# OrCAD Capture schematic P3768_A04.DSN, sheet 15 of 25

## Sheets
15 0010_PRE-REG 3V3: size Custom
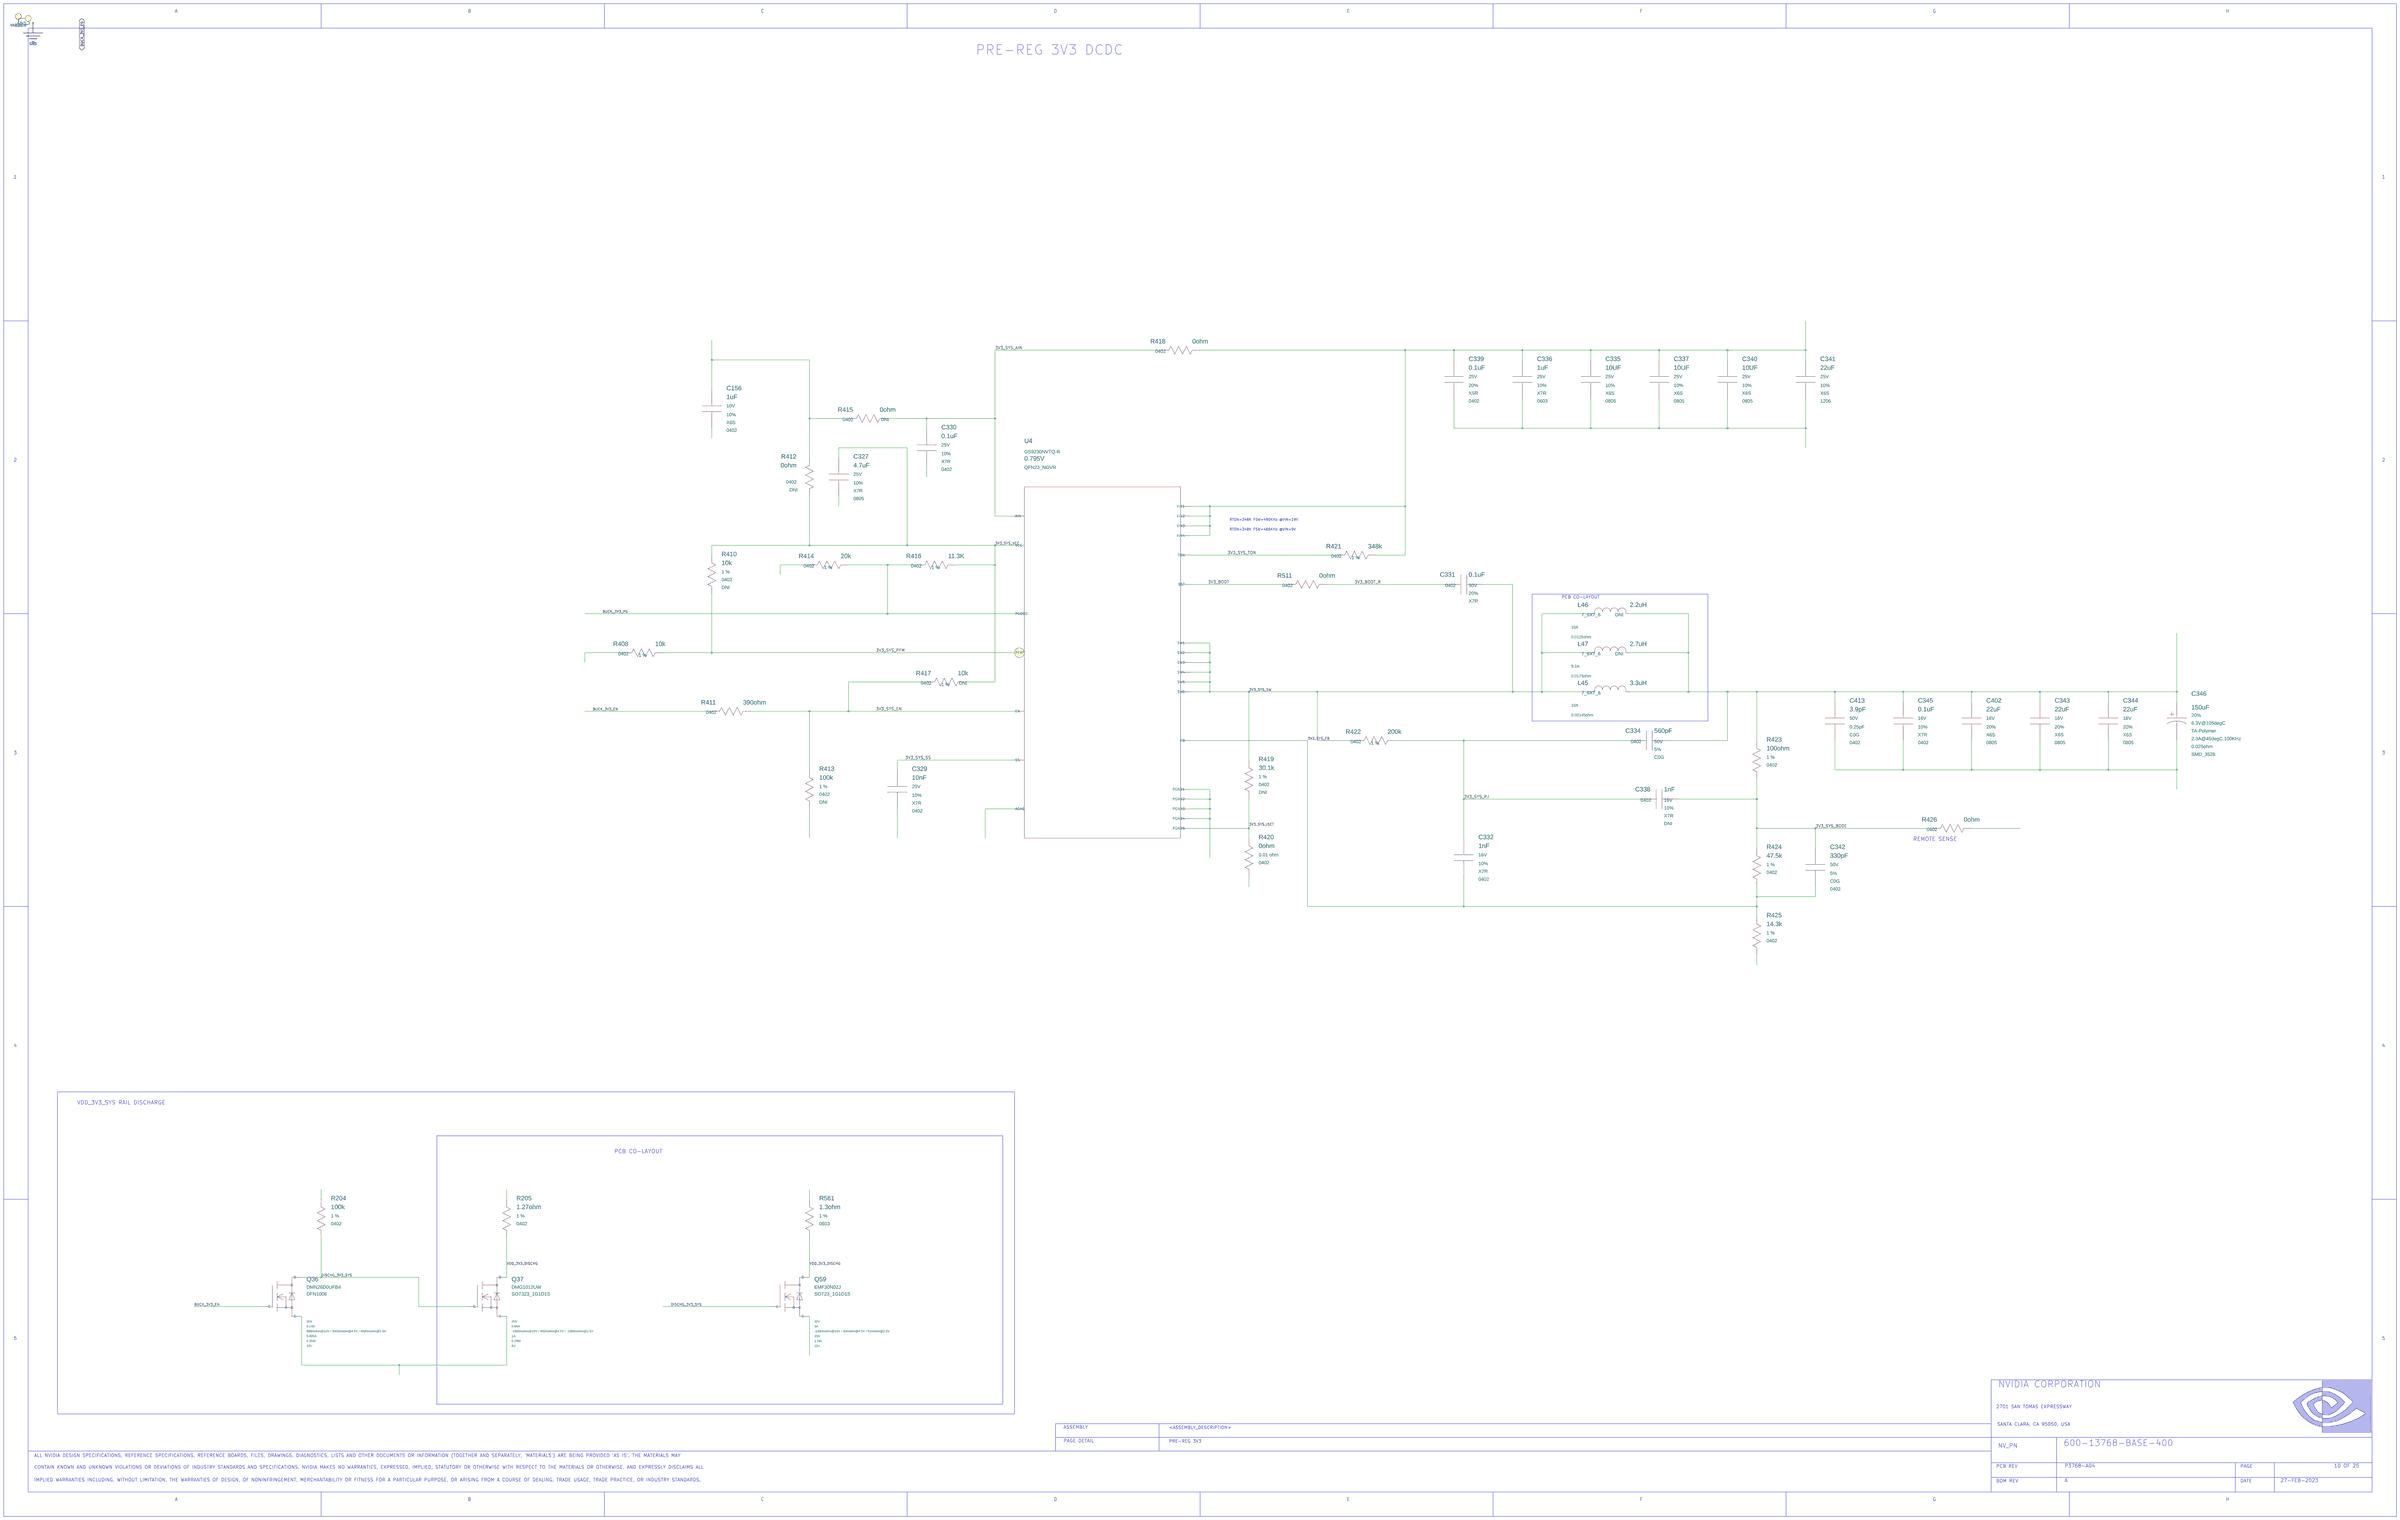
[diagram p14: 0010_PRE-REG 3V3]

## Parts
C156  1uF  [0402]
C327  4.7uF  [0805U]
C329  10nF  [0402]
C330  0.1uF  [0402]
C331  0.1uF  [0402]
C332  1nF  [0402]
C334  560pF  [0402]
C335  10UF  [0805U]
C336  1uF  [0603]
C337  10UF  [0805U]
C338  1nF  [0402]
C339  0.1uF  [0402]
C340  10UF  [0805U]
C341  22uF  [1206U]
C342  330pF  [0402]
C343  22uF  [0805U]
C344  22uF  [0805U]
C345  0.1uF  [0402]
C346  150uF  [CAP_SMD_3528]
C402  22uF  [0805U]
C413  3.9pF  [0402]
L45  3.3uH  [IND_NONRKO_SMD_075X075_B]
L46  2.2uH  [IND_NONRKO_SMD_069X069]
L47  2.7uH  [IND_NONRKO_SMD_075X075_B]
Q36  Q_FET_N_ENH  [DFET_003_SMD_010X006_B]
Q37  Q_FET_N_ENH  [SOT323]
Q59  Q_FET_N_ENH  [SOT23]
R204  100k  [0402]
R205  1.27ohm  [0402]
R408  10k  [0402]
R410  10k  [0402]
R411  390ohm  [0402]
R412  0ohm  [0402]
R413  100k  [0402]
R414  20k  [0402]
R415  0ohm  [0402]
R416  11.3K  [0402]
R417  10k  [0402]
R418  0ohm  [0402]
R419  30.1k  [0402]
R420  0ohm  [0402]
R421  348k  [0402]
R422  200k  [0402]
R423  100ohm  [0402]
R424  47.5k  [0402]
R425  14.3k  [0402]
R426  0ohm  [0402]
R511  0ohm  [0402]
R561  1.3ohm  [0603]
U4  0.795V  [QFN023Q_P050_0040_T028X011_T028X014]

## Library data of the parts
C156 = C#1: ASSEMBLY: PS_3V3; CDS_LIB: discrete; CDS_PART_NAME: C_0402-1UF,X6S,10%,10V,032-0776-000; CDS_PHYS_PART_NAME: C_0402-1UF,X6S,10%,10V,032-0776-000-032-0776-000,1UF; CDS_SEC: 1; CHIPS_PART_NAME: C; DEVICE_TYPENAME: C_0402-1UFX6S1010V032-0776-000-032-0776-0001UF; DRAWING: @P3768_A04_LIB.P3768_A04(SCH_1):PAGE10; MAT: X6S; MAX_VOLTAGE: 10V; NV_PN: 032-0776-000; PATH: I129; PHYS_PAGE: 10; PSPICETEMPLATE: X^@REFDES  %1    %2   @NV_PN; ROT: 0; SEC: 1; SIGNAL_MODEL: nv_cap; TOL: 10%; VER: 1; XY: (-8500,5550)
C327 = C#1: ASSEMBLY: PS_3V3; CDS_LIB: discrete; CDS_PART_NAME: C_0805-4.7UF,X7R,10%,25V,032-0207-000; CDS_PHYS_PART_NAME: C_0805-4.7UF,X7R,10%,25V,032-0207-000-032-0207-000,4.7UF; CDS_SEC: 1; CHIPS_PART_NAME: C; DEVICE_TYPENAME: C_0805-47UFX7R1025V032-0207-000-032-0207-00047UF; DRAWING: @P3768_A04_LIB.P3768_A04(SCH_1):PAGE10; MAT: X7R; MAX_VOLTAGE: 25V; NV_PN: 032-0207-000; PACK_TYPE: 0805; PATH: I80; PHYS_PAGE: 10; PSPICETEMPLATE: X^@REFDES  %1    %2   @NV_PN; ROT: 0; SEC: 1; SIGNAL_MODEL: nv_cap; TOL: 10%; VER: 1; XY: (-7850,5200)
C329 = C#1: ASSEMBLY: PS_3V3; CDS_LIB: discrete; CDS_PART_NAME: C_0402-10NF,X7R,10%,25V,036-0019-000; CDS_PHYS_PART_NAME: C_0402-10NF,X7R,10%,25V,036-0019-000-036-0019-000,10NF; CDS_SEC: 1; CHIPS_PART_NAME: C; DEVICE_TYPENAME: C_0402-10NFX7R1025V036-0019-000-036-0019-00010NF; DRAWING: @P3768_A04_LIB.P3768_A04(SCH_1):PAGE10; MAT: X7R; MAX_VOLTAGE: 25V; NV_PN: 036-0019-000; PATH: I117; PHYS_PAGE: 10; PSPICETEMPLATE: X^@REFDES  %1    %2   @NV_PN; ROT: 0; SEC: 1; SIGNAL_MODEL: nv_cap; TOL: 10%; VER: 1; XY: (-7550,3600)
C330 = C#1: ASSEMBLY: PS_3V3; CDS_LIB: discrete; CDS_PART_NAME: C_0402-0.1UF,X7R,10%,25V,032-1700-000; CDS_PHYS_PART_NAME: C_0402-0.1UF,X7R,10%,25V,032-1700-000-0.1UF,032-1700-000; CDS_SEC: 1; CHIPS_PART_NAME: C; DEVICE_TYPENAME: C_0402-01UFX7R1025V032-1700-000-01UF032-1700-000; DRAWING: @P3768_A04_LIB.P3768_A04(SCH_1):PAGE10; MAT: X7R; MAX_VOLTAGE: 25V; NV_PN: 032-1700-000; PATH: I83; PHYS_PAGE: 10; PSPICETEMPLATE: X^@REFDES  %1    %2   @NV_PN; ROT: 0; SEC: 1; SIGNAL_MODEL: nv_cap; TOL: 10%; VER: 1; XY: (-7400,5350)
C331 = C: ASSEMBLY: PS_5V; CDS_LIB: discrete; CDS_PART_NAME: C_0402-0.1UF,X7R,20%,50V,032-0892-000; CDS_PHYS_PART_NAME: C_0402-0.1UF,X7R,20%,50V,032-0892-000-0.1UF,032-0892-000; CDS_SEC: 1; DEVICE_TYPENAME: C_0402-01UFX7R2050V032-0892-000-01UF032-0892-000; DRAWING: @P3768_A04_LIB.P3768_A04(SCH_1):PAGE10; MAT: X7R; MAX_VOLTAGE: 50V; NV_PN: 032-0892-000; PATH: I87; PHYS_PAGE: 10; PSPICETEMPLATE: X^@REFDES  %1    %2   @NV_PN; ROT: 0; SEC: 1; SIGNAL_MODEL: nv_cap; TOL: 20%; VER: 2; XY: (-4650,4650)
C332 = C#1: ASSEMBLY: PS_3V3; CDS_LIB: discrete; CDS_PART_NAME: C_0402-1NF,X7R,10%,16V,036-0012-000; CDS_PHYS_PART_NAME: C_0402-1NF,X7R,10%,16V,036-0012-000-036-0012-000,1NF; CDS_SEC: 1; CHIPS_PART_NAME: C; DEVICE_TYPENAME: C_0402-1NFX7R1016V036-0012-000-036-0012-0001NF; DRAWING: @P3768_A04_LIB.P3768_A04(SCH_1):PAGE10; MAT: X7R; MAX_VOLTAGE: 16V; NV_PN: 036-0012-000; PATH: I124; PHYS_PAGE: 10; PSPICETEMPLATE: X^@REFDES  %1    %2   @NV_PN; ROT: 0; SEC: 1; SIGNAL_MODEL: nv_cap; TOL: 10%; VER: 1; XY: (-4650,3250)
C334 = C: ASSEMBLY: PS_3V3; CDS_LIB: discrete; CDS_PART_NAME: C_0402-560PF,C0G,5%,50V,035-0295-000; CDS_PHYS_PART_NAME: C_0402-560PF,C0G,5%,50V,035-0295-000-035-0295-000,560PF; CDS_SEC: 1; DEVICE_TYPENAME: C_0402-560PFC0G550V035-0295-000-035-0295-000560PF; DRAWING: @P3768_A04_LIB.P3768_A04(SCH_1):PAGE10; MAT: C0G; MAX_VOLTAGE: 50V; NV_PN: 035-0295-000; PATH: I183; PHYS_PAGE: 10; ROT: 0; SEC: 1; SIGNAL_MODEL: nv_cap; TOL: 5%; VER: 2; XY: (-3700,3850)
C335 = C#1: ASSEMBLY: PS_3V3; CDS_LIB: discrete; CDS_PART_NAME: C_0805-10UF,X6S,10%,25V,032-0728-000; CDS_PHYS_PART_NAME: C_0805-10UF,X6S,10%,25V,032-0728-000-032-0728-000,10UF; CDS_SEC: 1; CHIPS_PART_NAME: C; DEVICE_TYPENAME: C_0805-10UFX6S1025V032-0728-000-032-0728-00010UF; DRAWING: @P3768_A04_LIB.P3768_A04(SCH_1):PAGE10; MAT: X6S; MAX_VOLTAGE: 25V; NV_PN: 032-0728-000; PACK_TYPE: 0805; PATH: I151; PHYS_PAGE: 10; PSPICETEMPLATE: X^@REFDES  %1    %2   @NV_PN; ROT: 0; SEC: 1; SIGNAL_MODEL: nv_cap; TOL: 10%; VER: 1; XY: (-4000,5700)
C336 = C#1: ASSEMBLY: PS_3V3; CDS_LIB: discrete; CDS_PART_NAME: C_0603-1UF,X7R,10%,25V,032-0253-000; CDS_PHYS_PART_NAME: C_0603-1UF,X7R,10%,25V,032-0253-000-032-0253-000,1UF; CDS_SEC: 1; CHIPS_PART_NAME: C; DEVICE_TYPENAME: C_0603-1UFX7R1025V032-0253-000-032-0253-0001UF; DRAWING: @P3768_A04_LIB.P3768_A04(SCH_1):PAGE10; MAT: X7R; MAX_VOLTAGE: 25V; NV_PN: 032-0253-000; PATH: I180; PHYS_PAGE: 10; PSPICETEMPLATE: X^@REFDES  %1    %2   @NV_PN; ROT: 0; SEC: 1; SIGNAL_MODEL: nv_cap; TOL: 10%; VER: 1; XY: (-4350,5700)
C337 = C#1: ASSEMBLY: PS_3V3; CDS_LIB: discrete; CDS_PART_NAME: C_0805-10UF,X6S,10%,25V,032-0728-000; CDS_PHYS_PART_NAME: C_0805-10UF,X6S,10%,25V,032-0728-000-032-0728-000,10UF; CDS_SEC: 1; CHIPS_PART_NAME: C; DEVICE_TYPENAME: C_0805-10UFX6S1025V032-0728-000-032-0728-00010UF; DRAWING: @P3768_A04_LIB.P3768_A04(SCH_1):PAGE10; MAT: X6S; MAX_VOLTAGE: 25V; NV_PN: 032-0728-000; PACK_TYPE: 0805; PATH: I152; PHYS_PAGE: 10; PSPICETEMPLATE: X^@REFDES  %1    %2   @NV_PN; ROT: 0; SEC: 1; SIGNAL_MODEL: nv_cap; TOL: 10%; VER: 1; XY: (-3650,5700)
C338 = C: ASSEMBLY: PS_3V3; CDS_LIB: discrete; CDS_PART_NAME: C_0402-1NF,X7R,10%,16V,036-0012-000; CDS_PHYS_PART_NAME: C_0402-1NF,X7R,10%,16V,036-0012-000-036-0012-000,1NF; CDS_SEC: 1; DEVICE_TYPENAME: C_0402-1NFX7R1016V036-0012-000-036-0012-0001NF; DRAWING: @P3768_A04_LIB.P3768_A04(SCH_1):PAGE10; MAT: X7R; MAX_VOLTAGE: 16V; NV_PN: 036-0012-000; PATH: I127; PHYS_PAGE: 10; PSPICETEMPLATE: X^@REFDES  %1    %2   @NV_PN; ROT: 0; SEC: 1; SIGNAL_MODEL: nv_cap; SKU: DNI; TOL: 10%; VER: 2; XY: (-3650,3550)
C339 = C#1: ASSEMBLY: PS_3V3; CDS_LIB: discrete; CDS_PART_NAME: C_0402-0.1UF,X5R,20%,25V,039-0208-000; CDS_PHYS_PART_NAME: C_0402-0.1UF,X5R,20%,25V,039-0208-000-0.1UF,039-0208-000; CDS_SEC: 1; CHIPS_PART_NAME: C; DEVICE_TYPENAME: C_0402-01UFX5R2025V039-0208-000-01UF039-0208-000; DRAWING: @P3768_A04_LIB.P3768_A04(SCH_1):PAGE10; MAT: X5R; MAX_VOLTAGE: 25V; NV_PN: 039-0208-000; PATH: I182; PHYS_PAGE: 10; ROT: 0; SEC: 1; SIGNAL_MODEL: nv_cap; TOL: 20%; VER: 1; XY: (-4700,5700)
C340 = C#1: ASSEMBLY: PS_3V3; CDS_LIB: discrete; CDS_PART_NAME: C_0805-10UF,X6S,10%,25V,032-0728-000; CDS_PHYS_PART_NAME: C_0805-10UF,X6S,10%,25V,032-0728-000-032-0728-000,10UF; CDS_SEC: 1; CHIPS_PART_NAME: C; DEVICE_TYPENAME: C_0805-10UFX6S1025V032-0728-000-032-0728-00010UF; DRAWING: @P3768_A04_LIB.P3768_A04(SCH_1):PAGE10; MAT: X6S; MAX_VOLTAGE: 25V; NV_PN: 032-0728-000; PACK_TYPE: 0805; PATH: I153; PHYS_PAGE: 10; PSPICETEMPLATE: X^@REFDES  %1    %2   @NV_PN; ROT: 0; SEC: 1; SIGNAL_MODEL: nv_cap; TOL: 10%; VER: 1; XY: (-3300,5700)
C341 = C#1: ASSEMBLY: PS_3V3; CDS_LIB: discrete; CDS_PART_NAME: C_1206-22UF,X6S,10%,25V,032-1215-000; CDS_PHYS_PART_NAME: C_1206-22UF,X6S,10%,25V,032-1215-000-032-1215-000,22UF; CDS_SEC: 1; CHIPS_PART_NAME: C; DEVICE_TYPENAME: C_1206-22UFX6S1025V032-1215-000-032-1215-00022UF; DRAWING: @P3768_A04_LIB.P3768_A04(SCH_1):PAGE10; MAT: X6S; MAX_VOLTAGE: 25V; NV_PN: 032-1215-000; PACK_TYPE: 1206; PATH: I179; PHYS_PAGE: 10; ROT: 0; SEC: 1; SIGNAL_MODEL: nv_cap; TOL: 10%; VER: 1; XY: (-2900,5700)
C342 = C#1: ASSEMBLY: PS_3V3; CDS_LIB: discrete; CDS_PART_NAME: C_0402-330PF,C0G,5%,50V,035-0066-000; CDS_PHYS_PART_NAME: C_0402-330PF,C0G,5%,50V,035-0066-000-035-0066-000,330PF; CDS_SEC: 1; CHIPS_PART_NAME: C; DEVICE_TYPENAME: C_0402-330PFC0G550V035-0066-000-035-0066-000330PF; DRAWING: @P3768_A04_LIB.P3768_A04(SCH_1):PAGE10; MAT: C0G; MAX_VOLTAGE: 50V; NV_PN: 035-0066-000; PATH: I95; PHYS_PAGE: 10; PSPICETEMPLATE: X^@REFDES  %1    %2   @NV_PN; ROT: 0; SEC: 1; SIGNAL_MODEL: nv_cap; TOL: 5%; VER: 1; XY: (-2850,3200)
C343 = C#1: ASSEMBLY: PS_3V3; CDS_LIB: discrete; CDS_PART_NAME: C_0805-22UF,X6S,20%,16V,032-0559-000; CDS_PHYS_PART_NAME: C_0805-22UF,X6S,20%,16V,032-0559-000-032-0559-000,22UF; CDS_SEC: 1; CHIPS_PART_NAME: C; DEVICE_TYPENAME: C_0805-22UFX6S2016V032-0559-000-032-0559-00022UF; DRAWING: @P3768_A04_LIB.P3768_A04(SCH_1):PAGE10; MAT: X6S; MAX_VOLTAGE: 16V; NV_PN: 032-0559-000; PACK_TYPE: 0805; PATH: I97; PHYS_PAGE: 10; PSPICETEMPLATE: X^@REFDES  %1    %2   @NV_PN; ROT: 0; SEC: 1; SIGNAL_MODEL: nv_cap; TOL: 20%; VER: 1; XY: (-1700,3950)
C344 = C#1: ASSEMBLY: PS_3V3; CDS_LIB: discrete; CDS_PART_NAME: C_0805-22UF,X6S,20%,16V,032-0559-000; CDS_PHYS_PART_NAME: C_0805-22UF,X6S,20%,16V,032-0559-000-032-0559-000,22UF; CDS_SEC: 1; CHIPS_PART_NAME: C; DEVICE_TYPENAME: C_0805-22UFX6S2016V032-0559-000-032-0559-00022UF; DRAWING: @P3768_A04_LIB.P3768_A04(SCH_1):PAGE10; MAT: X6S; MAX_VOLTAGE: 16V; NV_PN: 032-0559-000; PACK_TYPE: 0805; PATH: I99; PHYS_PAGE: 10; PSPICETEMPLATE: X^@REFDES  %1    %2   @NV_PN; ROT: 0; SEC: 1; SIGNAL_MODEL: nv_cap; TOL: 20%; VER: 1; XY: (-1350,3950)
C345 = C#1: ASSEMBLY: PS_3V3; CDS_LIB: discrete; CDS_PART_NAME: C_0402-0.1UF,X7R,10%,16V,032-0793-000; CDS_PHYS_PART_NAME: C_0402-0.1UF,X7R,10%,16V,032-0793-000-0.1UF,032-0793-000; CDS_SEC: 1; CHIPS_PART_NAME: C; DEVICE_TYPENAME: C_0402-01UFX7R1016V032-0793-000-01UF032-0793-000; DRAWING: @P3768_A04_LIB.P3768_A04(SCH_1):PAGE10; MAT: X7R; MAX_VOLTAGE: 16V; NV_PN: 032-0793-000; PATH: I100; PHYS_PAGE: 10; PSPICETEMPLATE: X^@REFDES  %1    %2   @NV_PN; ROT: 0; SEC: 1; SIGNAL_MODEL: nv_cap; TOL: 10%; VER: 1; XY: (-2400,3950)
C346 = C_POL: ASSEMBLY: PS_3V3; CDS_LIB: discrete; CDS_PART_NAME: C_POL_SMD_3528-150UF,TA-POLYMER,20%,6.3V@105DEGC,0.025OHM,9.999UH,2.3A@45DEGC,100KHZ,032-0681-000; CDS_PHYS_PART_NAME: C_POL_SMD_3528-150UF,TA-POLYMER,20%,6.3V@105DEGC,0.025OHM,9.999UH,2.3A@45DEGC,100KHZ,032-0681-000-032-0681-000,150UF; CDS_SEC: 1; DEVICE_TYPENAME: C_POL_SMD_3528-150UFTA-POLYMER2063V105DEGC0025OHM9999UH23A45DEGC100KHZ032-0681-000-032-0681-000150UF; DRAWING: @P3768_A04_LIB.P3768_A04(SCH_1):PAGE10; ESL: 9.999uH; ESR: 0.025ohm; MAT: TA-Polymer; MAX_VOLTAGE: 6.3V@105degC; NV_PN: 032-0681-000; PACK_TYPE: SMD_3528; PATH: I148; PHYS_PAGE: 10; RIPPLE_CURRENT: 2.3A@45degC,100KHz; ROT: 0; SEC: 1; SIGNAL_MODEL: nv_capp; TOL: 20%; VER: 1; XY: (-1000,3950)
C402 = C#1: ASSEMBLY: PS_3V3; CDS_LIB: discrete; CDS_PART_NAME: C_0805-22UF,X6S,20%,16V,032-0559-000; CDS_PHYS_PART_NAME: C_0805-22UF,X6S,20%,16V,032-0559-000-032-0559-000,22UF; CDS_SEC: 1; CHIPS_PART_NAME: C; DEVICE_TYPENAME: C_0805-22UFX6S2016V032-0559-000-032-0559-00022UF; DRAWING: @P3768_A04_LIB.P3768_A04(SCH_1):PAGE10; MAT: X6S; MAX_VOLTAGE: 16V; NV_PN: 032-0559-000; PACK_TYPE: 0805; PATH: I147; PHYS_PAGE: 10; PSPICETEMPLATE: X^@REFDES  %1    %2   @NV_PN; ROT: 0; SEC: 1; SIGNAL_MODEL: nv_cap; TOL: 20%; VER: 1; XY: (-2050,3950)
C413 = C#1: ASSEMBLY: PS_3V3; CDS_LIB: discrete; CDS_PART_NAME: C_0402-3.9PF,C0G,0.25PF,50V,035-0029-000; CDS_PHYS_PART_NAME: C_0402-3.9PF,C0G,0.25PF,50V,035-0029-000-035-0029-000,3.9PF; CDS_SEC: 1; CHIPS_PART_NAME: C; DEVICE_TYPENAME: C_0402-39PFC0G025PF50V035-0029-000-035-0029-00039PF; DRAWING: @P3768_A04_LIB.P3768_A04(SCH_1):PAGE10; MAT: C0G; MAX_VOLTAGE: 50V; NV_PN: 035-0029-000; PATH: I198; PHYS_PAGE: 10; ROT: 0; SEC: 1; SIGNAL_MODEL: nv_cap; TOL: 0.25pF; VER: 1; XY: (-2750,3950)
L45 = L: ASSEMBLY: PS_3V3; CDS_LIB: discrete; CDS_PART_NAME: L_7_6X7_6-3.3UH,COMPOSITE,20%,10A,12.3A,0.02145OHM,[ ]@[ ],29MHZ,130-1404-000; CDS_PHYS_PART_NAME: L_7_6X7_6-3.3UH,COMPOSITE,20%,10A,12.3A,0.02145OHM,[ ]@[ ],29MHZ,130-1404-000-130-1404-000,3.3UH; CDS_SEC: 1; CONTINUOUS_CURRENT: 10A; DC_RESISTANCE: 0.02145ohm; DEVICE_TYPENAME: L_7_6X7_6-33UHCOMPOSITE2010A123A002145OHM29MHZ130-1404-000-130-1404-00033UH; DRAWING: @P3768_A04_LIB.P3768_A04(SCH_1):PAGE10; MAT: Composite; MAX_CURRENT: 12.3A; NV_PN: 130-1404-000; PACK_TYPE: 7_6X7_6; PATH: I184; PHYS_PAGE: 10; Q: [ ]@[ ]; ROT: 0; SEC: 1; SELF_RESONANCE_FREQ: 29MHz; SIGNAL_MODEL: nv_ind; TOL: 20%; VER: 1; XY: (-3900,4100)
L46 = L: ASSEMBLY: PS_3V3; CDS_LIB: discrete; CDS_PART_NAME: L_7_6X7_6-2.2UH,ALLOY POWDER,20%,10A,12A,0.0125OHM,50@300KHZ,0HZ,130-1236-000; CDS_PHYS_PART_NAME: L_7_6X7_6-2.2UH,ALLOY POWDER,20%,10A,12A,0.0125OHM,50@300KHZ,0HZ,130-1236-000-130-1236-000,2.2UH; CDS_SEC: 1; CONTINUOUS_CURRENT: 10A; DC_RESISTANCE: 0.0125ohm; DEVICE_TYPENAME: L_7_6X7_6-22UHALLOYPOWDER2010A12A00125OHM50300KHZ0HZ130-1236-000-130-1236-00022UH; DRAWING: @P3768_A04_LIB.P3768_A04(SCH_1):PAGE10; MAT: Alloy Powder; MAX_CURRENT: 12A; NV_PN: 130-1236-000; PACK_TYPE: 7_6X7_6; PATH: I186; PHYS_PAGE: 10; Q: 50@300KHz; ROT: 0; SEC: 1; SELF_RESONANCE_FREQ: 0Hz; SIGNAL_MODEL: nv_ind; SKU: DNI; TOL: 20%; VER: 1; XY: (-3900,4500)
L47 = L: ASSEMBLY: PS_3V3; CDS_LIB: discrete; CDS_PART_NAME: L_7_6X7_6-2.7UH,COMPOSITE,20%,9.2A,12.8A,0.0173OHM,[ ]@[ ],32MHZ,130-1439-000; CDS_PHYS_PART_NAME: L_7_6X7_6-2.7UH,COMPOSITE,20%,9.2A,12.8A,0.0173OHM,[ ]@[ ],32MHZ,130-1439-000-130-1439-000,2.7UH; CDS_SEC: 1; CONTINUOUS_CURRENT: 9.2A; DC_RESISTANCE: 0.0173ohm; DEVICE_TYPENAME: L_7_6X7_6-27UHCOMPOSITE2092A128A00173OHM32MHZ130-1439-000-130-1439-00027UH; DRAWING: @P3768_A04_LIB.P3768_A04(SCH_1):PAGE10; MAT: Composite; MAX_CURRENT: 12.8A; NV_PN: 130-1439-000; PACK_TYPE: 7_6X7_6; PATH: I185; PHYS_PAGE: 10; Q: [ ]@[ ]; ROT: 0; SEC: 1; SELF_RESONANCE_FREQ: 32MHz; SIGNAL_MODEL: nv_ind; SKU: DNI; TOL: 20%; VER: 1; XY: (-3900,4300)
Q36 = Q_FET_N_ENH#1: ASSEMBLY: PS_3V3; CDS_LIB: discrete; CDS_PART_NAME: Q_FET_N_ENH_DFN1006-DMN26D0UFB4,20V,999MOHM@10V / 3000MOHM@4.5V / 4000MOHM@2.5V,0.14A,0.805A,10V,0.35W,999NC@10V / 0NC@4.5V / 999NC@2.5V,300-0868-000; CDS_PHYS_PART_NAME: Q_FET_N_ENH_DFN1006-DMN26D0UFB4,20V,999MOHM@10V / 3000MOHM@4.5V / 4000MOHM@2.5V,0.14A,0.805A,10V,0.35W,999NC@10V / 0NC@4.5V / B; CDS_SEC: 1; CONTINUOUS_CURRENT: 0.14A; CaptureCellPackProp: Q_FET_N_ENH##1; DEVICE_TYPENAME: Q_FET_N_ENH_DFN1006-DMN26D0UFB420V999MOHM10V3000MOHM45V4000MOHM25V014A0805A10V035W999NC10V0NC45VB; DRAWING: @P3768_A04_LIB.P3768_A04(SCH_1):PAGE10; MAX_CURRENT: 0.805A; MAX_VOLTAGE: 20V; MAX_WATTAGE: 0.35W; NV_NAME: DMN26D0UFB4; NV_PN: 300-0868-000; PACK_TYPE: DFN1006; PATH: I199; PHYS_PAGE: 10; Q_G: 999nC@10V / 0nC@4.5V / 999nC@2.5V; ROT: 0; R_DS_ON: 999mohm@10V / 3000mohm@4.5V / 4000mohm@2.5V; SEC: 1; VER: 2; V_BE_GS: 10V; XY: (-10700,1000)
Q37 = Q_FET_N_ENH#1: ASSEMBLY: PS_3V3; CDS_LIB: discrete; CDS_PART_NAME: Q_FET_N_ENH_SOT323_1G1D1S-DMG1012UW,20V,-1000MOHM@10V / 450MOHM@4.5V / -1000MOHM@2.5V,0.64A,1A,6V,0.29W,[ ]@10V / 0.7366NC@4.5V / [ ]@2.5V,300-0790-000; CDS_PHYS_PART_NAME: Q_FET_N_ENH_SOT323_1G1D1S-DMG1012UW,20V,-1000MOHM@10V / 450MOHM@4.5V / -1000MOHM@2.5V,0.64A,1A,6V,0.29W,[ ]@10V / 0.7366NC@4.5B; CDS_SEC: 1; CONTINUOUS_CURRENT: 0.64A; CaptureCellPackProp: Q_FET_N_ENH##1; DEVICE_TYPENAME: Q_FET_N_ENH_SOT323_1G1D1S-DMG1012UW20V-1000MOHM10V450MOHM45V-1000MOHM25V064A1A6V029W10V07366NC45B; DRAWING: @P3768_A04_LIB.P3768_A04(SCH_1):PAGE10; MAX_CURRENT: 1A; MAX_VOLTAGE: 20V; MAX_WATTAGE: 0.29W; NV_NAME: DMG1012UW; NV_PN: 300-0790-000; PACK_TYPE: SOT323_1G1D1S; PATH: I207; PHYS_PAGE: 10; Q_G: [ ]@10V / 0.7366nC@4.5V / [ ]@2.5V; ROT: 0; R_DS_ON: -1000mohm@10V / 450mohm@4.5V / -1000mohm@2.5V; SEC: 1; VER: 2; V_BE_GS: 6V; XY: (-9650,1000)
Q59 = Q_FET_N_ENH#1: ASSEMBLY: PS_3V3; CDS_LIB: discrete; CDS_PART_NAME: Q_FET_N_ENH_SOT23_1G1D1S-EMF30N02J,20V,-1000MOHM@10V / 30MOHM@4.5V / 51MOHM@2.5V,5A,20A,12V,1.5W,[ ]@10V / 10NC@4.5V / [ ]@2.5V,300-0609-000; CDS_PHYS_PART_NAME: Q_FET_N_ENH_SOT23_1G1D1S-EMF30N02J,20V,-1000MOHM@10V / 30MOHM@4.5V / 51MOHM@2.5V,5A,20A,12V,1.5W,[ ]@10V / 10NC@4.5V / [ ]@2.5B; CDS_SEC: 1; CONTINUOUS_CURRENT: 5A; CaptureCellPackProp: Q_FET_N_ENH##1; DEVICE_TYPENAME: Q_FET_N_ENH_SOT23_1G1D1S-EMF30N02J20V-1000MOHM10V30MOHM45V51MOHM25V5A20A12V15W10V10NC45V25B; DRAWING: @P3768_A04_LIB.P3768_A04(SCH_1):PAGE10; MAX_CURRENT: 20A; MAX_VOLTAGE: 20V; MAX_WATTAGE: 1.5W; NV_NAME: EMF30N02J; NV_PN: 300-0609-000; PACK_TYPE: SOT23_1G1D1S; PATH: I201; PHYS_PAGE: 10; Q_G: [ ]@10V / 10nC@4.5V / [ ]@2.5V; ROT: 0; R_DS_ON: -1000mohm@10V / 30mohm@4.5V / 51mohm@2.5V; SEC: 1; VER: 2; V_BE_GS: 12V; XY: (-8100,1000)
R204 = R: ASSEMBLY: PS_3V3; CDS_LIB: discrete; CDS_PART_NAME: R_0402-100K,1 %,62.5MW,195-0005-000; CDS_PHYS_PART_NAME: R_0402-100K,1 %,62.5MW,195-0005-000-100K,195-0005-000; CDS_SEC: 1; DEVICE_TYPENAME: R_0402-100K1625MW195-0005-000-100K195-0005-000; DRAWING: @P3768_A04_LIB.P3768_A04(SCH_1):PAGE10; MAX_WATTAGE: 62.5mW; NV_PN: 195-0005-000; PATH: I48; PHYS_PAGE: 10; PSPICETEMPLATE: X^@REFDES  %1    %2   @NV_PN; ROT: 0; SEC: 1; SIGNAL_MODEL: nv_res; TOL: 1 %; VER: 2; XY: (-10500,1400)
R205 = R: ASSEMBLY: PS_3V3; CDS_LIB: discrete; CDS_PART_NAME: R_0402-1.27OHM,1 %,62.5MW,195-1356-000; CDS_PHYS_PART_NAME: R_0402-1.27OHM,1 %,62.5MW,195-1356-000-1.27OHM,195-1356-000; CDS_SEC: 1; DEVICE_TYPENAME: R_0402-127OHM1625MW195-1356-000-127OHM195-1356-000; DRAWING: @P3768_A04_LIB.P3768_A04(SCH_1):PAGE10; MAX_WATTAGE: 62.5mW; NV_PN: 195-1356-000; PATH: I206; PHYS_PAGE: 10; ROT: 0; SEC: 1; TOL: 1 %; VER: 2; XY: (-9550,1400)
R408 = R#1: ASSEMBLY: PS_3V3; CDS_LIB: discrete; CDS_PART_NAME: R_0402-10K,1 %,62.5MW,195-0004-000; CDS_PHYS_PART_NAME: R_0402-10K,1 %,62.5MW,195-0004-000-10K,195-0004-000; CDS_SEC: 1; CHIPS_PART_NAME: R; DEVICE_TYPENAME: R_0402-10K1625MW195-0004-000-10K195-0004-000; DRAWING: @P3768_A04_LIB.P3768_A04(SCH_1):PAGE10; MAX_WATTAGE: 62.5mW; NV_PN: 195-0004-000; PATH: I59; PHYS_PAGE: 10; PSPICETEMPLATE: X^@REFDES  %1    %2   @NV_PN; ROT: 0; SEC: 1; SIGNAL_MODEL: nv_res; TOL: 1 %; VER: 1; XY: (-8850,4300)
R410 = R: ASSEMBLY: PS_3V3; CDS_LIB: discrete; CDS_PART_NAME: R_0402-10K,1 %,62.5MW,195-0004-000; CDS_PHYS_PART_NAME: R_0402-10K,1 %,62.5MW,195-0004-000-10K,195-0004-000; CDS_SEC: 1; DEVICE_TYPENAME: R_0402-10K1625MW195-0004-000-10K195-0004-000; DRAWING: @P3768_A04_LIB.P3768_A04(SCH_1):PAGE10; MAX_WATTAGE: 62.5mW; NV_PN: 195-0004-000; PATH: I70; PHYS_PAGE: 10; PSPICETEMPLATE: X^@REFDES  %1    %2   @NV_PN; ROT: 0; SEC: 1; SIGNAL_MODEL: nv_res; SKU: DNI; TOL: 1 %; VER: 2; XY: (-8500,4700)
R411 = R#1: ASSEMBLY: PS_3V3; CDS_LIB: discrete; CDS_PART_NAME: R_0402-390OHM,5 %,62.5MW,195-0583-000; CDS_PHYS_PART_NAME: R_0402-390OHM,5 %,62.5MW,195-0583-000-195-0583-000,390OHM; CDS_SEC: 1; CHIPS_PART_NAME: R; DEVICE_TYPENAME: R_0402-390OHM5625MW195-0583-000-195-0583-000390OHM; DRAWING: @P3768_A04_LIB.P3768_A04(SCH_1):PAGE10; MAX_WATTAGE: 62.5mW; NV_PN: 195-0583-000; PATH: I60; PHYS_PAGE: 10; PSPICETEMPLATE: X^@REFDES  %1    %2   @NV_PN; ROT: 0; SEC: 1; SIGNAL_MODEL: nv_res; TOL: 5 %; VER: 1; XY: (-8400,4000)
R412 = R: ASSEMBLY: PS_3V3; CDS_LIB: discrete; CDS_PART_NAME: R_0402-0OHM,0.05 OHM,62.5MW,195-2655-000; CDS_PHYS_PART_NAME: R_0402-0OHM,0.05 OHM,62.5MW,195-2655-000-0OHM,195-2655-000; CDS_SEC: 1; DEVICE_TYPENAME: R_0402-0OHM005OHM625MW195-2655-000-0OHM195-2655-000; DRAWING: @P3768_A04_LIB.P3768_A04(SCH_1):PAGE10; MAX_WATTAGE: 62.5mW; NV_PN: 195-2655-000; PATH: I79; PHYS_PAGE: 10; PSPICETEMPLATE: X^@REFDES  %1    %2   @NV_PN; ROT: 2; SEC: 1; SIGNAL_MODEL: nv_res; SKU: DNI; TOL: 0.05 ohm; VER: 2; XY: (-8000,5200)
R413 = R: ASSEMBLY: PS_3V3; CDS_LIB: discrete; CDS_PART_NAME: R_0402-100K,1 %,62.5MW,195-0005-000; CDS_PHYS_PART_NAME: R_0402-100K,1 %,62.5MW,195-0005-000-100K,195-0005-000; CDS_SEC: 1; DEVICE_TYPENAME: R_0402-100K1625MW195-0005-000-100K195-0005-000; DRAWING: @P3768_A04_LIB.P3768_A04(SCH_1):PAGE10; MAX_WATTAGE: 62.5mW; NV_PN: 195-0005-000; PATH: I116; PHYS_PAGE: 10; PSPICETEMPLATE: X^@REFDES  %1    %2   @NV_PN; ROT: 0; SEC: 1; SIGNAL_MODEL: nv_res; SKU: DNI; TOL: 1 %; VER: 2; XY: (-8000,3600)
R414 = R#1: ASSEMBLY: PS_3V3; CDS_LIB: discrete; CDS_PART_NAME: R_0402-20K,1 %,62.5MW,195-0150-000; CDS_PHYS_PART_NAME: R_0402-20K,1 %,62.5MW,195-0150-000-195-0150-000,20K; CDS_SEC: 1; CHIPS_PART_NAME: R; DEVICE_TYPENAME: R_0402-20K1625MW195-0150-000-195-0150-00020K; DRAWING: @P3768_A04_LIB.P3768_A04(SCH_1):PAGE10; MAX_WATTAGE: 62.5mW; NV_PN: 195-0150-000; PATH: I77; PHYS_PAGE: 10; PSPICETEMPLATE: X^@REFDES  %1    %2   @NV_PN; ROT: 0; SEC: 1; SIGNAL_MODEL: nv_res; TOL: 1 %; VER: 1; XY: (-7900,4750)
R415 = R#1: ASSEMBLY: PS_3V3; CDS_LIB: discrete; CDS_PART_NAME: R_0402-0OHM,0.05 OHM,62.5MW,195-2655-000; CDS_PHYS_PART_NAME: R_0402-0OHM,0.05 OHM,62.5MW,195-2655-000-0OHM,195-2655-000; CDS_SEC: 1; CHIPS_PART_NAME: R; DEVICE_TYPENAME: R_0402-0OHM005OHM625MW195-2655-000-0OHM195-2655-000; DRAWING: @P3768_A04_LIB.P3768_A04(SCH_1):PAGE10; MAX_WATTAGE: 62.5mW; NV_PN: 195-2655-000; PATH: I84; PHYS_PAGE: 10; PSPICETEMPLATE: X^@REFDES  %1    %2   @NV_PN; ROT: 0; SEC: 1; SIGNAL_MODEL: nv_res; SKU: DNI; TOL: 0.05 ohm; VER: 1; XY: (-7700,5500)
R416 = R#1: ASSEMBLY: PS_3V3; CDS_LIB: discrete; CDS_PART_NAME: R_0402-11.3K,1 %,62.5MW,195-0030-000; CDS_PHYS_PART_NAME: R_0402-11.3K,1 %,62.5MW,195-0030-000-11.3K,195-0030-000; CDS_SEC: 1; CHIPS_PART_NAME: R; DEVICE_TYPENAME: R_0402-113K1625MW195-0030-000-113K195-0030-000; DRAWING: @P3768_A04_LIB.P3768_A04(SCH_1):PAGE10; MAX_WATTAGE: 62.5MW; NV_PN: 195-0030-000; PATH: I81; PHYS_PAGE: 10; PSPICETEMPLATE: X^@REFDES  %1    %2   @NV_PN; ROT: 0; SEC: 1; SIGNAL_MODEL: nv_res; TOL: 1 %; VER: 1; XY: (-7350,4750)
R417 = R#1: ASSEMBLY: PS_3V3; CDS_LIB: discrete; CDS_PART_NAME: R_0402-10K,1 %,62.5MW,195-0004-000; CDS_PHYS_PART_NAME: R_0402-10K,1 %,62.5MW,195-0004-000-10K,195-0004-000; CDS_SEC: 1; CHIPS_PART_NAME: R; DEVICE_TYPENAME: R_0402-10K1625MW195-0004-000-10K195-0004-000; DRAWING: @P3768_A04_LIB.P3768_A04(SCH_1):PAGE10; MAX_WATTAGE: 62.5mW; NV_PN: 195-0004-000; PATH: I72; PHYS_PAGE: 10; PSPICETEMPLATE: X^@REFDES  %1    %2   @NV_PN; ROT: 0; SEC: 1; SIGNAL_MODEL: nv_res; SKU: DNI; TOL: 1 %; VER: 1; XY: (-7300,4150)
R418 = R#1: ASSEMBLY: PS_3V3; CDS_LIB: discrete; CDS_PART_NAME: R_0402-0OHM,0.05 OHM,62.5MW,195-2655-000; CDS_PHYS_PART_NAME: R_0402-0OHM,0.05 OHM,62.5MW,195-2655-000-0OHM,195-2655-000; CDS_SEC: 1; CHIPS_PART_NAME: R; DEVICE_TYPENAME: R_0402-0OHM005OHM625MW195-2655-000-0OHM195-2655-000; DRAWING: @P3768_A04_LIB.P3768_A04(SCH_1):PAGE10; MAX_WATTAGE: 62.5mW; NV_PN: 195-2655-000; PATH: I89; PHYS_PAGE: 10; ROT: 0; SEC: 1; SIGNAL_MODEL: nv_res; TOL: 0.05 ohm; VER: 1; XY: (-6100,5850)
R419 = R: ASSEMBLY: PS_3V3; CDS_LIB: discrete; CDS_PART_NAME: R_0402-30.1K,1 %,62.5MW,195-0235-000; CDS_PHYS_PART_NAME: R_0402-30.1K,1 %,62.5MW,195-0235-000-195-0235-000,30.1K; CDS_SEC: 1; DEVICE_TYPENAME: R_0402-301K1625MW195-0235-000-195-0235-000301K; DRAWING: @P3768_A04_LIB.P3768_A04(SCH_1):PAGE10; MAX_WATTAGE: 62.5mW; NV_PN: 195-0235-000; PATH: I123; PHYS_PAGE: 10; ROT: 0; SEC: 1; SIGNAL_MODEL: nv_res; SKU: DNI; TOL: 1 %; VER: 2; XY: (-5750,3650)
R420 = R: ASSEMBLY: PS_3V3; CDS_LIB: discrete; CDS_PART_NAME: R_0402-0OHM,0.01 OHM,0.125W,195-1691-000; CDS_PHYS_PART_NAME: R_0402-0OHM,0.01 OHM,0.125W,195-1691-000-0OHM,195-1691-000; CDS_SEC: 1; DEVICE_TYPENAME: R_0402-0OHM001OHM0125W195-1691-000-0OHM195-1691-000; DRAWING: @P3768_A04_LIB.P3768_A04(SCH_1):PAGE10; MAX_WATTAGE: 0.125W; NV_PN: 195-1691-000; PATH: I122; PHYS_PAGE: 10; ROT: 0; SEC: 1; SIGNAL_MODEL: nv_res; TOL: 0.01 ohm; VER: 2; XY: (-5750,3250)
R421 = R#1: ASSEMBLY: PS_3V3; CDS_LIB: discrete; CDS_PART_NAME: R_0402-348K,1 %,62.5MW,195-0266-000; CDS_PHYS_PART_NAME: R_0402-348K,1 %,62.5MW,195-0266-000-195-0266-000,348K; CDS_SEC: 1; CHIPS_PART_NAME: R; DEVICE_TYPENAME: R_0402-348K1625MW195-0266-000-195-0266-000348K; DRAWING: @P3768_A04_LIB.P3768_A04(SCH_1):PAGE10; MAX_WATTAGE: 62.5mW; NV_PN: 195-0266-000; PATH: I200; PHYS_PAGE: 10; ROT: 0; SEC: 1; TOL: 1 %; VER: 1; XY: (-5200,4800)
R422 = R#1: ASSEMBLY: PS_3V3; CDS_LIB: discrete; CDS_PART_NAME: R_0402-200K,1 %,62.5MW,195-0151-000; CDS_PHYS_PART_NAME: R_0402-200K,1 %,62.5MW,195-0151-000-195-0151-000,200K; CDS_SEC: 1; CHIPS_PART_NAME: R; DEVICE_TYPENAME: R_0402-200K1625MW195-0151-000-195-0151-000200K; DRAWING: @P3768_A04_LIB.P3768_A04(SCH_1):PAGE10; MAX_WATTAGE: 62.5mW; NV_PN: 195-0151-000; PATH: I125; PHYS_PAGE: 10; PSPICETEMPLATE: X^@REFDES  %1    %2   @NV_PN; ROT: 0; SEC: 1; SIGNAL_MODEL: nv_res; TOL: 1 %; VER: 1; XY: (-5100,3850)
R423 = R: ASSEMBLY: PS_3V3; CDS_LIB: discrete; CDS_PART_NAME: R_0402-100OHM,1 %,62.5MW,195-0002-000; CDS_PHYS_PART_NAME: R_0402-100OHM,1 %,62.5MW,195-0002-000-100OHM,195-0002-000; CDS_SEC: 1; DEVICE_TYPENAME: R_0402-100OHM1625MW195-0002-000-100OHM195-0002-000; DRAWING: @P3768_A04_LIB.P3768_A04(SCH_1):PAGE10; MAX_WATTAGE: 62.5mW; NV_PN: 195-0002-000; PATH: I96; PHYS_PAGE: 10; PSPICETEMPLATE: X^@REFDES  %1    %2   @NV_PN; ROT: 0; SEC: 1; SIGNAL_MODEL: nv_res; TOL: 1 %; VER: 2; XY: (-3150,3750)
R424 = R: ASSEMBLY: PS_3V3; CDS_LIB: discrete; CDS_PART_NAME: R_0402-47.5K,1 %,62.5MW,195-0330-000; CDS_PHYS_PART_NAME: R_0402-47.5K,1 %,62.5MW,195-0330-000-195-0330-000,47.5K; CDS_SEC: 1; DEVICE_TYPENAME: R_0402-475K1625MW195-0330-000-195-0330-000475K; DRAWING: @P3768_A04_LIB.P3768_A04(SCH_1):PAGE10; MAX_WATTAGE: 62.5mW; NV_PN: 195-0330-000; PATH: I188; PHYS_PAGE: 10; ROT: 0; SEC: 1; SIGNAL_MODEL: nv_res; TOL: 1 %; VER: 2; XY: (-3150,3200)
R425 = R: ASSEMBLY: PS_3V3; CDS_LIB: discrete; CDS_PART_NAME: R_0402-14.3K,1 %,62.5MW,195-0080-000; CDS_PHYS_PART_NAME: R_0402-14.3K,1 %,62.5MW,195-0080-000-14.3K,195-0080-000; CDS_SEC: 1; DEVICE_TYPENAME: R_0402-143K1625MW195-0080-000-143K195-0080-000; DRAWING: @P3768_A04_LIB.P3768_A04(SCH_1):PAGE10; MAX_WATTAGE: 62.5mW; NV_PN: 195-0080-000; PATH: I190; PHYS_PAGE: 10; ROT: 0; SEC: 1; SIGNAL_MODEL: nv_res; TOL: 1 %; VER: 2; XY: (-3150,2850)
R426 = R#1: ASSEMBLY: PS_3V3; CDS_LIB: discrete; CDS_PART_NAME: R_0402-0OHM,0.05 OHM,62.5MW,195-2655-000; CDS_PHYS_PART_NAME: R_0402-0OHM,0.05 OHM,62.5MW,195-2655-000-0OHM,195-2655-000; CDS_SEC: 1; CHIPS_PART_NAME: R; DEVICE_TYPENAME: R_0402-0OHM005OHM625MW195-2655-000-0OHM195-2655-000; DRAWING: @P3768_A04_LIB.P3768_A04(SCH_1):PAGE10; MAX_WATTAGE: 62.5mW; NV_PN: 195-2655-000; PATH: I98; PHYS_PAGE: 10; PSPICETEMPLATE: X^@REFDES  %1    %2   @NV_PN; ROT: 0; SEC: 1; SIGNAL_MODEL: nv_res; TOL: 0.05 ohm; VER: 1; XY: (-2150,3400)
R511 = R#1: ASSEMBLY: PS_3V3; CDS_LIB: discrete; CDS_PART_NAME: R_0402-0OHM,0.05 OHM,62.5MW,195-2655-000; CDS_PHYS_PART_NAME: R_0402-0OHM,0.05 OHM,62.5MW,195-2655-000-0OHM,195-2655-000; CDS_SEC: 1; CHIPS_PART_NAME: R; DEVICE_TYPENAME: R_0402-0OHM005OHM625MW195-2655-000-0OHM195-2655-000; DRAWING: @P3768_A04_LIB.P3768_A04(SCH_1):PAGE10; MAX_WATTAGE: 62.5mW; NV_PN: 195-2655-000; PATH: I197; PHYS_PAGE: 10; PSPICETEMPLATE: X^@REFDES  %1    %2   @NV_PN; ROT: 0; SEC: 1; SIGNAL_MODEL: nv_res; TOL: 0.05 ohm; VER: 1; XY: (-5450,4650)
R561 = R: ASSEMBLY: PS_3V3; CDS_LIB: discrete; CDS_PART_NAME: R_0603-1.3OHM,1 %,0.1W,195-4021-000; CDS_PHYS_PART_NAME: R_0603-1.3OHM,1 %,0.1W,195-4021-000-1.3OHM,195-4021-000; CDS_SEC: 1; DEVICE_TYPENAME: R_0603-13OHM101W195-4021-000-13OHM195-4021-000; DRAWING: @P3768_A04_LIB.P3768_A04(SCH_1):PAGE10; MAX_WATTAGE: 0.1W; NV_PN: 195-4021-000; PATH: I205; PHYS_PAGE: 10; ROT: 0; SEC: 1; TOL: 1 %; VER: 2; XY: (-8000,1400)
U4 = U_BUCK_FET_1PH: ASSEMBLY: PS_3V3; CDS_LIB: power_supply; CDS_PART_NAME: U_BUCK_FET_1PH_QFN23_NOVR-GS9230NVTQ-R,BUCK,1PH,600KHZ,NONE,0.795V..20V,1%,0.795V,28V,11A,2.5W,316-0538-000; CDS_PHYS_PART_NAME: U_BUCK_FET_1PH_QFN23_NOVR-GS9230NVTQ-R,BUCK,1PH,600KHZ,NONE,0.795V..20V,1%,0.795V,28V,11A,2.5W,316-0538-000-0.795V,316-0538-000; CDS_SEC: 1; DEVICE_TYPENAME: U_BUCK_FET_1PH_QFN23_NOVR-GS9230NVTQ-RBUCK1PH600KHZNONE0795V20V10795V28V11A25W316-0538-000-0795V316-0538-000; DRAWING: @P3768_A04_LIB.P3768_A04(SCH_1):PAGE10; MAX_CURRENT: 11A; MAX_VOLTAGE: 28V; MAX_WATTAGE: 2.5W; MODE: Buck; NV_NAME: GS9230NVTQ-R; NV_PN: 316-0538-000; OUTPUT_VOLTAGE: 0.795V..20V; PACK_TYPE: QFN23_NOVR; PATH: I119; PHASES: 1Ph; PHYS_PAGE: 10; PROGRAMMABLE: None; ROT: 0; SEC: 1; SWITCHING_FREQ: 600KHz; TOL: 1%; VER: 1; XY: (-6500,4250)

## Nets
3V3_BOOT: R511.1 U4.20(BST)
3V3_BOOT_R: C331.1 R511.2
3V3_SYS_AIN: C330.1 R415.2 R418.1 U4.7(AIN)
3V3_SYS_BODE: C338.2 C342.1 R423.2 R424.1 R426.1
3V3_SYS_EN: R411.2 R413.1 R417.1 U4.2(EN)
3V3_SYS_FB: C332.2 C342.2 R424.2 R425.1 U4.5(FB)
3V3_SYS_ISET: R419.2 R420.1 U4.19(PGND5)
3V3_SYS_PFM: R408.2 R410.2 U4.3(PFM*)
3V3_SYS_RJ: C332.1 C334.1 C338.1 R422.2
3V3_SYS_SS: C329.1 U4.23(SS)
3V3_SYS_SW: C331.2 L45.1 L46.1 L47.1 R419.1 R422.1 U4.10(SW1) U4.11(SW2) U4.16(SW3) U4.17(SW4) U4.18(SW5) U4.25(SW6)
3V3_SYS_TON: R421.1 U4.6(TON)
3V3_SYS_VCC: C327.1 R410.1 R412.2 R416.2 R417.2 U4.21(VCC)
5V_LDO_OUT: C156.1 R412.1 R415.1 ; also on sheet 16
GND: C156.2 C327.2 C329.2 C330.2 C335.2 C336.2 C337.2 C339.2 C340.2 C341.2 C343.2 C344.2 C345.2 C346.2 C402.2 C413.2 Q36.2(S) Q37.2(S) Q59.2(S) R408.1 R413.2 R414.1 R420.2 R425.2 U4.4(AGND) U4.12(PGND1) U4.13(PGND2) U4.14(PGND3) U4.15(PGND4) ; also on sheet 1 2 3 4 5 6 7 8 9 10 11 12 13 14 16 17 18 19 21 25
VDD_3V3_DISCHG: Q37.3(D) Q59.3(D) R205.2 R561.2
VDD_3V3_SYS: C334.2 C343.1 C344.1 C345.1 C346.1 C402.1 C413.1 L45.2 L46.2 L47.2 R205.1 R423.1 R426.2 R561.1 ; also on sheet 1 2 3 4 5 6 7 8 11 12 14 19 20 21
VDD_5V_SYS: R204.1 ; also on sheet 1 2 8 9 10 11 12 13 14 16 17 21
VDD_CVB: C335.1 C336.1 C337.1 C339.1 C340.1 C341.1 R418.2 R421.2 U4.8(VIN1) U4.9(VIN2) U4.22(VIN3) U4.24(VIN4) ; also on sheet 16 18
BUCK_3V3_EN: Q36.1(G) R411.1 ; also on sheet 13
BUCK_3V3_PG: R414.2 R416.1 U4.1(PGOOD) ; also on sheet 8 11 13 14
DISCHG_3V3_SYS: Q36.3(D) Q37.1(G) Q59.1(G) R204.2

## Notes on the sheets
sheet 15
- A
- B
- C
- D
- E
- F
- G
- H
- PRE-REG 3V3 DCDC
- 1
- 1
- 2
- 2
- RTON=348K FSW=490KHz @VIN=19V
- RTON=348K FSW=466KHz @VIN=9V
- PCB CO-LAYOUT
- 3
- 3
- REMOTE SENSE
- 4
- 4
- VDD_3V3_SYS RAIL DISCHARGE
- PCB CO-LAYOUT
- 5
- 5
- NVIDIA CORPORATION
- 2701 SAN TOMAS EXPRESSWAY
- SANTA CLARA, CA 95050, USA
- ASSEMBLY
- <ASSEMBLY_DESCRIPTION>
- PAGE DETAIL
- PRE-REG 3V3
- 600-13768-BASE-400
- NV_PN
- ALL NVIDIA DESIGN SPECIFICATIONS, REFERENCE SPECIFICATIONS, REFERENCE BOARDS, FILES, DRAWINGS, DIAGNOSTICS, LISTS AND OTHER DOCUMENTS OR INFORMATION (TOGETHER AND SEPARATELY, 'MATERIALS') ARE BEING PROVIDED 'AS IS'. THE MATERIALS MAY
- P3768-A04
- 10 OF 25
- CONTAIN KNOWN AND UNKNOWN VIOLATIONS OR DEVIATIONS OF INDUSTRY STANDARDS AND SPECIFICATIONS. NVIDIA MAKES NO WARRANTIES, EXPRESSED, IMPLIED, STATUTORY OR OTHERWISE WITH RESPECT TO THE MATERIALS OR OTHERWISE, AND EXPRESSLY DISCLAIMS ALL
- PCB REV
- PAGE
- IMPLIED WARRANTIES INCLUDING, WITHOUT LIMITATION, THE WARRANTIES OF DESIGN, OF NONINFRINGEMENT, MERCHANTABILITY OR FITNESS FOR A PARTICULAR PURPOSE, OR ARISING FROM A COURSE OF DEALING, TRADE USAGE, TRADE PRACTICE, OR INDUSTRY STANDARDS.
- BOM REV
- A
- DATE
- 27-FEB-2023
- A
- B
- C
- D
- E
- F
- G
- H
